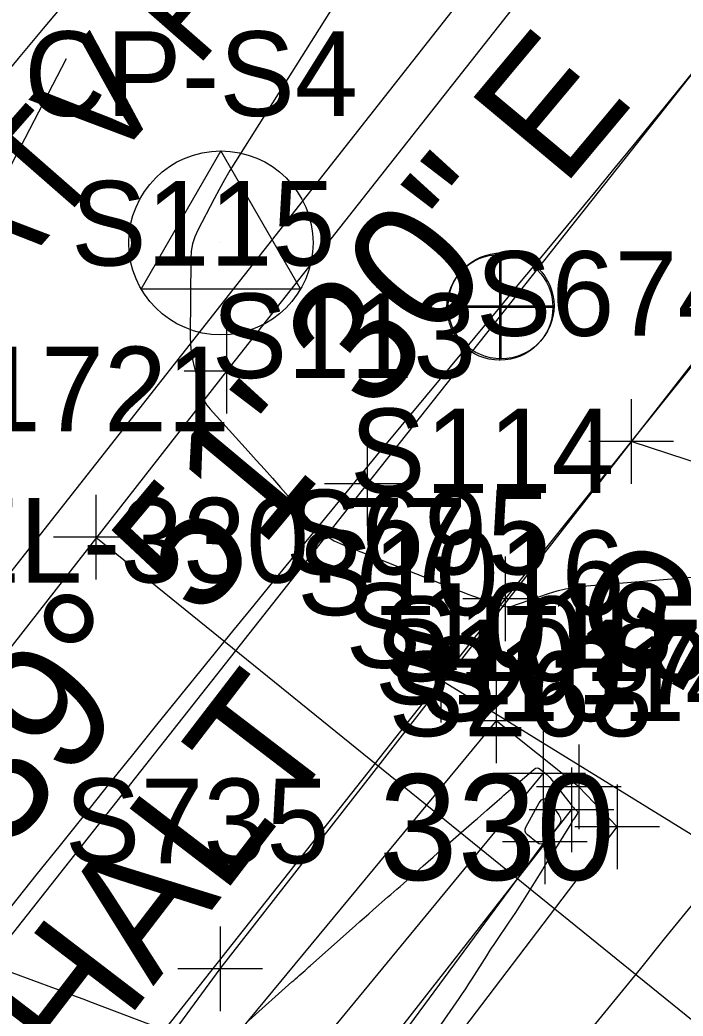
# Model space of a CAD drawing. Extents: x 816928 to 825690, y 436959 to 448212.
# Drawn here: x 819251.82 to 819283.14, y 445565.31 to 445612.41 of the extents above; entities that cross this region are included whole.
import ezdxf

# ---------------------------------------------------------------- set-up
doc = ezdxf.new("R2010")
doc.units = 0
for name, color, linetype in [('SURVEY - CENTERLINE - Preliminary', 7, 'Continuous'), ('SURVEY - CENTERLINE - Preliminary - Development', 7, 'Continuous'), ('SURVEY - CENTERLINE - Preliminary Text', 7, 'Continuous'), ('SURVEY - CONTOURS - Index with Text', 7, 'Continuous'), ('SURVEY - CONTOURS - Intermediate with optional Text', 7, 'Continuous'), ('SURVEY - CONTROL with Text', 7, 'Continuous'), ('SURVEY - DRAINAGE - Area Shapes', 7, 'Continuous'), ('SURVEY - DTM - Breaklines', 7, 'Continuous'), ('SURVEY - DTM - Breaklines - Points - Locators', 7, 'Continuous'), ('SURVEY - DTM - Breaklines - Points - Numbers', 7, 'Continuous'), ('SURVEY - PROPERTY - Parcels', 7, 'Continuous'), ('SURVEY - PROPERTY - ROW Lines', 7, 'Continuous'), ('SURVEY - TRANSPORTATION - Features', 7, 'Continuous'), ('SURVEY - TRANSPORTATION - Features - Points - Locators', 7, 'Continuous'), ('SURVEY - TRANSPORTATION - Features - Points - Numbers', 7, 'Continuous'), ('SURVEY - TRANSPORTATION - Features Text', 7, 'Continuous'), ('SURVEY - TRANSPORTATION - Roads', 7, 'Continuous'), ('SURVEY - TRANSPORTATION - Roads - Points - Locators', 7, 'Continuous'), ('SURVEY - TRANSPORTATION - Roads - Points - Numbers', 7, 'Continuous'), ('SURVEY - TRANSPORTATION - Roads Text', 7, 'Continuous'), ('SURVEY - UTILITIES - Cable (Underground) with Text', 7, 'Continuous'), ('SURVEY - UTILITIES - Gas - Points - Locators', 7, 'Continuous'), ('SURVEY - UTILITIES - Gas - Points - Numbers', 7, 'Continuous'), ('SURVEY - UTILITIES - Gas with Text', 7, 'Continuous'), ('SURVEY - UTILITIES - Poles and Miscellaneous - Points - Elevations', 7, 'Continuous'), ('SURVEY - UTILITIES - Water - Points - Locators', 7, 'Continuous'), ('SURVEY - UTILITIES - Water - Points - Numbers', 7, 'Continuous'), ('SURVEY - UTILITIES - Water with Text', 7, 'Continuous'), ('SURVEY - VEGETATION - Features - Points - Locators', 7, 'Continuous'), ('SURVEY - VEGETATION - Features - Points - Numbers', 7, 'Continuous'), ('SURVEY - VEGETATION - Features with Text', 7, 'Continuous')]:
    doc.layers.add(name, color=color, linetype=linetype)

msp = doc.modelspace()

# ---------------------------------------------------------------- linework, layer by layer
at = {"layer": 'SURVEY - CENTERLINE - Preliminary'}
msp.add_line((819274.472, 445598.813), (819274.528, 445598.88), dxfattribs=at)
for centre, radius, start, end in [((818575.983, 446182.091), 910, 320.141729, 331.568854), ((818575.983, 446182.091), 910, 320.141729, 331.568854), ((820425.92, 444637.477), 1500, 140.141729, 144.598464), ((820425.92, 444637.477), 1500, 140.141729, 144.598464)]:
    msp.add_arc(centre, radius, start, end, dxfattribs=at)
at = {"layer": 'SURVEY - CENTERLINE - Preliminary - Development'}
for p, q in [((819274.472, 445601.313), (819274.472, 445596.313)), ((819274.528, 445601.38), (819274.528, 445596.38)), ((819276.972, 445598.813), (819271.972, 445598.813)), ((819277.028, 445598.88), (819272.028, 445598.88))]:
    msp.add_line(p, q, dxfattribs=at)
at = {"layer": 'SURVEY - CENTERLINE - Preliminary Text'}
for p, q in [((819274.472, 445598.813), (819274.472, 445598.813)), ((819274.528, 445598.88), (819274.528, 445598.88))]:
    msp.add_line(p, q, dxfattribs=at)
for centre in [(819274.491, 445598.819), (819274.547, 445598.887)]:
    msp.add_circle(centre, 2.5, dxfattribs=at)
at = {"layer": 'SURVEY - CONTOURS - Index with Text'}
for points in [[(819254, 445610.57), (819250.305, 445603.462)], [(819262.638, 445565.11), (819264.668, 445566.926), (819264.754, 445567.002), (819264.839, 445567.078), (819264.925, 445567.153), (819265.01, 445567.229), (819265.291, 445567.475), (819265.351, 445567.528), (819265.411, 445567.581), (819265.471, 445567.634), (819265.531, 445567.687), (819267.67, 445569.593), (819267.878, 445569.778), (819268.087, 445569.962), (819268.296, 445570.146), (819268.505, 445570.33), (819269.19, 445570.928), (819269.337, 445571.057), (819269.483, 445571.185), (819269.629, 445571.314), (819269.775, 445571.443), (819270.864, 445572.41), (819271.098, 445572.617), (819271.332, 445572.823), (819271.567, 445573.029), (819271.802, 445573.234), (819273.281, 445574.522), (819273.431, 445574.653), (819273.581, 445574.784), (819273.73, 445574.915), (819273.88, 445575.047), (819274.367, 445575.477), (819274.471, 445575.569), (819274.576, 445575.661), (819274.681, 445575.753), (819274.786, 445575.844), (819276.093, 445576.977), (819276.168, 445577.026), (819276.244, 445577.044), (819276.321, 445577.029), (819276.398, 445576.983), (819276.651, 445576.782), (819276.704, 445576.737), (819276.754, 445576.69), (819276.801, 445576.639), (819276.845, 445576.586), (819277.85, 445575.303), (819277.886, 445575.258), (819277.923, 445575.215), (819277.962, 445575.172), (819278.002, 445575.131), (819278.135, 445574.997), (819278.157, 445574.968), (819278.166, 445574.937), (819278.163, 445574.905), (819278.146, 445574.873), (819277.977, 445574.622), (819277.941, 445574.568), (819277.906, 445574.514), (819277.871, 445574.46), (819277.836, 445574.405), (819277.115, 445573.241), (819276.96, 445572.992), (819276.806, 445572.742), (819276.651, 445572.493), (819276.497, 445572.244), (819275.556, 445570.726), (819275.393, 445570.467), (819275.228, 445570.21), (819275.059, 445569.955), (819274.888, 445569.703), (819274.323, 445568.88), (819274.203, 445568.703), (819274.085, 445568.525), (819273.968, 445568.346), (819273.853, 445568.165), (819273.162, 445567.073), (819273.012, 445566.839), (819272.861, 445566.607), (819272.707, 445566.377), (819272.55, 445566.148), (819271.594, 445564.765)], [(819275.719, 445574.246), (819276.342, 445575.387), (819276.455, 445575.538), (819276.573, 445575.595), (819276.699, 445575.555), (819276.831, 445575.42), (819277.274, 445574.824), (819277.344, 445574.696), (819277.367, 445574.569), (819277.34, 445574.443), (819277.266, 445574.318), (819276.685, 445573.584), (819276.577, 445573.481), (819276.463, 445573.438), (819276.342, 445573.456), (819276.214, 445573.534), (819275.788, 445573.886), (819275.715, 445573.966), (819275.679, 445574.052), (819275.681, 445574.145), (819275.719, 445574.246)], [(819251.448, 445567.368), (819253.488, 445566.614), (819253.925, 445566.452), (819254.361, 445566.289), (819254.797, 445566.126), (819255.233, 445565.961), (819258.48, 445564.729)]]:
    msp.add_lwpolyline(points, dxfattribs=at)
at = {"layer": 'SURVEY - CONTOURS - Intermediate with optional Text'}
msp.add_lwpolyline([(819270.629, 445619.417), (819262.003, 445605.715), (819261.736, 445605.281), (819261.478, 445604.841), (819261.229, 445604.397), (819260.99, 445603.947), (819260.222, 445602.47), (819260.077, 445602.148), (819259.974, 445601.816), (819259.911, 445601.475), (819259.889, 445601.123), (819259.869, 445597.428), (819259.879, 445597.069), (819259.912, 445596.713), (819259.968, 445596.359), (819260.047, 445596.009), (819260.342, 445594.868), (819260.419, 445594.631), (819260.522, 445594.408), (819260.652, 445594.2), (819260.808, 445594.005), (819262.601, 445592.02), (819262.985, 445591.594), (819263.367, 445591.166), (819263.748, 445590.738), (819264.127, 445590.308), (819265.586, 445588.647), (819265.915, 445588.314), (819266.276, 445588.026), (819266.668, 445587.784), (819267.092, 445587.586), (819272.169, 445585.571), (819272.436, 445585.466), (819272.703, 445585.365), (819272.971, 445585.266), (819273.241, 445585.169), (819274.457, 445584.74), (819274.478, 445584.733), (819274.5, 445584.727), (819274.521, 445584.721), (819274.543, 445584.716), (819274.615, 445584.7), (819274.63, 445584.697), (819274.645, 445584.693), (819274.661, 445584.69), (819274.676, 445584.687), (819274.83, 445584.653), (819274.862, 445584.648), (819274.895, 445584.648), (819274.927, 445584.652), (819274.959, 445584.661), (819276.793, 445585.29), (819277.188, 445585.412), (819277.589, 445585.51), (819277.995, 445585.582), (819278.407, 445585.63), (819283.55, 445586.065)], dxfattribs=at)
at = {"layer": 'SURVEY - CONTROL with Text'}
for p, q in [((819261.315, 445606.216), (819257.547, 445599.691)), ((819265.082, 445599.691), (819261.315, 445606.216)), ((819261.315, 445601.866), (819261.315, 445601.866)), ((819257.547, 445599.691), (819265.082, 445599.691))]:
    msp.add_line(p, q, dxfattribs=at)
msp.add_circle((819261.315, 445601.866), 4.35, dxfattribs=at)
at = {"layer": 'SURVEY - DRAINAGE - Area Shapes'}
msp.add_line((819274.472, 445598.813), (819274.528, 445598.88), dxfattribs=at)
for centre, radius, start, end in [((818575.983, 446182.091), 910, 320.141729, 331.568854), ((820425.92, 444637.477), 1500, 140.141729, 144.598464)]:
    msp.add_arc(centre, radius, start, end, dxfattribs=at)
at = {"layer": 'SURVEY - DTM - Breaklines'}
for points in [[(819380.404, 445755.141), (819355.578, 445711.888), (819328.616, 445669.931), (819299.268, 445629.736), (819268.215, 445590.476), (819237.204, 445551.148), (819207.272, 445511.316), (819178.097, 445471.355), (819148.961, 445430.516), (819120.831, 445389.41), (819092.595, 445348.525), (819063.764, 445307.701), (819034.576, 445266.965), (819005.716, 445226.512), (818977.706, 445187.397)], [(819115.743, 445352.623), (819116.501, 445348.532), (819118.762, 445346.334), (819121.805, 445346.034), (819151.273, 445387.488), (819170.031, 445419.1), (819198.511, 445465.669), (819205.76, 445465.616), (819229.822, 445502.933), (819247.854, 445531.915), (819280.031, 445574.26), (819278.221, 445576.151), (819274.311, 445579.267), (819242.916, 445541.289), (819216.533, 445504.811), (819186.916, 445462.104), (819160.05, 445422.329), (819116.797, 445352.316)], [(819118.629, 445350.898), (819165.289, 445424.101), (819196.182, 445467.268), (819224.41, 445508.114), (819242.999, 445536.052), (819276.537, 445576.778)], [(819121.197, 445348.347), (819148.072, 445388.457), (819146.917, 445389.221), (819167.079, 445422.999), (819197.484, 445466.128), (819224.892, 445507.372), (819245.683, 445533.866), (819277.871, 445575.058)]]:
    msp.add_lwpolyline(points, dxfattribs=at)
at = {"layer": 'SURVEY - DTM - Breaklines - Points - Locators'}
for p, q in [((819268.215, 445592.476), (819268.215, 445588.476)), ((819270.215, 445590.476), (819266.215, 445590.476)), ((819274.311, 445581.267), (819274.311, 445577.267)), ((819276.311, 445579.267), (819272.311, 445579.267)), ((819276.537, 445578.778), (819276.537, 445574.778)), ((819278.221, 445578.151), (819278.221, 445574.151)), ((819277.871, 445577.058), (819277.871, 445573.058)), ((819278.537, 445576.778), (819274.537, 445576.778)), ((819280.221, 445576.151), (819276.221, 445576.151)), ((819280.031, 445576.26), (819280.031, 445572.26)), ((819279.871, 445575.058), (819275.871, 445575.058)), ((819282.031, 445574.26), (819278.031, 445574.26))]:
    msp.add_line(p, q, dxfattribs=at)
at = {"layer": 'SURVEY - PROPERTY - Parcels'}
for radius, end in [(1525, 144.574738), (1475, 144.598464)]:
    msp.add_arc((820425.92, 444637.477), radius, 140.141729, end, dxfattribs=at)
at = {"layer": 'SURVEY - PROPERTY - ROW Lines'}
for radius, end in [(1525, 144.574738), (1525, 144.574738), (1475, 144.598464), (1475, 144.598464)]:
    msp.add_arc((820425.92, 444637.477), radius, 140.141729, end, dxfattribs=at)
at = {"layer": 'SURVEY - TRANSPORTATION - Features'}
for points in [[(819290.371, 445604.569), (819297.011, 445596.352), (819322.259, 445582.842), (819319.545, 445574.083), (819291.995, 445588.779), (819280.694, 445592.472)], [(819318.745, 445574.129), (819306.664, 445553.05), (819293.667, 445563.515), (819294.599, 445567.059), (819271.707, 445581.193)]]:
    msp.add_lwpolyline(points, dxfattribs=at)
at = {"layer": 'SURVEY - TRANSPORTATION - Features - Points - Locators'}
for p, q in [((819280.694, 445594.472), (819280.694, 445590.472)), ((819282.694, 445592.472), (819278.694, 445592.472)), ((819271.707, 445583.193), (819271.707, 445579.193)), ((819273.707, 445581.193), (819269.707, 445581.193))]:
    msp.add_line(p, q, dxfattribs=at)
at = {"layer": 'SURVEY - TRANSPORTATION - Roads'}
for points in [[(819372.417, 445760.729), (819347.536, 445716.465), (819327.358, 445684.931), (819320.732, 445674.576), (819313.086, 445663.907), (819291.72, 445634.092), (819261.573, 445595.794), (819230.52, 445556.026), (819202.59, 445519.473), (819200.025, 445516.115), (819183.78, 445493.817), (819171.491, 445476.948), (819142.501, 445435.003), (819121.554, 445405.003), (819114.313, 445394.631), (819108.813, 445386.861), (819085.629, 445354.103), (819056.538, 445311.65), (819028.029, 445272.038), (818998.985, 445231.035), (818970.783, 445191.785), (818984.089, 445181.723)], [(819389.734, 445754.855), (819362.957, 445707.555), (819358.085, 445699.888), (819346.624, 445681.852), (819335.583, 445664.476), (819305.378, 445623.327), (819290.371, 445604.569), (819280.694, 445592.472), (819274.745, 445585.035), (819271.707, 445581.193), (819243.267, 445545.212), (819213.411, 445505.8), (819184.164, 445465.705), (819155.799, 445425.75), (819127.747, 445384.791), (819108.123, 445356.526), (819098.861, 445343.186), (819090.273, 445331.1), (819070.114, 445302.733), (819042.351, 445263.277), (819039.074, 445258.681), (819026.695, 445241.322), (819012.76, 445221.779), (818984.089, 445181.723)]]:
    msp.add_lwpolyline(points, dxfattribs=at)
at = {"layer": 'SURVEY - TRANSPORTATION - Roads - Points - Locators'}
for p, q in [((819261.573, 445597.794), (819261.573, 445593.794)), ((819263.573, 445595.794), (819259.573, 445595.794)), ((819274.745, 445587.035), (819274.745, 445583.035)), ((819276.745, 445585.035), (819272.745, 445585.035))]:
    msp.add_line(p, q, dxfattribs=at)
at = {"layer": 'SURVEY - UTILITIES - Gas - Points - Locators'}
for p, q in [((819255.402, 445589.957), (819255.402, 445585.957)), ((819257.402, 445587.957), (819253.402, 445587.957))]:
    msp.add_line(p, q, dxfattribs=at)
at = {"layer": 'SURVEY - UTILITIES - Gas with Text'}
for points in [[(818968.105, 445195.328), (818969.738, 445197.267), (819012.001, 445253.658), (819064.107, 445326.037), (819122.078, 445408.8), (819183.152, 445497.068), (819237.635, 445568.809), (819293.129, 445639.42), (819349.073, 445723.122), (819383.091, 445785.202)], [(819255.402, 445587.957), (819296.534, 445554.619), (819316.051, 445542.116), (819330.474, 445549.407), (819356.758, 445566.69)]]:
    msp.add_lwpolyline(points, dxfattribs=at)
at = {"layer": 'SURVEY - UTILITIES - Water - Points - Locators'}
for p, q in [((819261.281, 445569.542), (819261.281, 445565.542)), ((819263.281, 445567.542), (819259.281, 445567.542))]:
    msp.add_line(p, q, dxfattribs=at)
at = {"layer": 'SURVEY - UTILITIES - Water with Text'}
msp.add_lwpolyline([(818803.235, 444799.745), (818822.09, 444847.157), (818840.807, 444894.989), (818859.419, 444943.113), (818878.417, 444989.731), (818897.247, 445035.659), (818918.394, 445078.737), (818943.016, 445121.017), (818943.424, 445156.253), (818947.564, 445166.115), (818971.795, 445201.192), (819041.117, 445261.897), (819085.564, 445324.056), (819114.437, 445364.745), (819142.589, 445406.123), (819261.281, 445567.542), (819325.961, 445650.567), (819357.336, 445697.813), (819381.766, 445739.87), (819404.905, 445782.998)], dxfattribs=at)
at = {"layer": 'SURVEY - VEGETATION - Features - Points - Locators'}
for p, q in [((819276.613, 445575.546), (819276.613, 445571.546)), ((819278.613, 445573.546), (819274.613, 445573.546))]:
    msp.add_line(p, q, dxfattribs=at)
at = {"layer": 'SURVEY - VEGETATION - Features with Text'}
msp.add_line((819228.505, 445508.335), (819276.613, 445573.546), dxfattribs=at)

# ---------------------------------------------------------------- texts
at = {"layer": 'SURVEY - CENTERLINE - Preliminary Text'}
msp.add_text('N 39%%d 51\' 30" E', height=6, rotation=50.1417, dxfattribs=at).set_placement((819245.984, 445566.742))
at = {"layer": 'SURVEY - CONTOURS - Index with Text'}
msp.add_text('330', height=5, dxfattribs=at).set_placement((819268.773, 445571.746))
at = {"layer": 'SURVEY - CONTROL with Text'}
msp.add_text('CP-S4', height=4, dxfattribs=at).set_placement((819252.027, 445607.866))
at = {"layer": 'SURVEY - DTM - Breaklines - Points - Numbers'}
for s, p in [('S113', (819260.879, 445595.476)), ('S1016', (819264.913, 445584.267)), ('S1018', (819267.202, 445581.778)), ('S1015', (819268.933, 445581.151)), ('S1017', (819268.583, 445580.058)), ('S1014', (819270.743, 445579.26))]:
    msp.add_text(s, height=4, dxfattribs=at).set_placement(p)
at = {"layer": 'SURVEY - TRANSPORTATION - Features - Points - Numbers'}
for s, p in [('S674', (819273.358, 445597.472)), ('S695', (819264.371, 445586.193))]:
    msp.add_text(s, height=4, dxfattribs=at).set_placement(p)
at = {"layer": 'SURVEY - TRANSPORTATION - Features Text'}
msp.add_text('GRV. DR.', height=5, rotation=330.7672, dxfattribs=at).set_placement((819277.597, 445583.831))
at = {"layer": 'SURVEY - TRANSPORTATION - Roads - Points - Numbers'}
for s, p in [('S115', (819254.237, 445600.794)), ('S114', (819267.409, 445590.035))]:
    msp.add_text(s, height=4, dxfattribs=at).set_placement(p)
at = {"layer": 'SURVEY - TRANSPORTATION - Roads Text'}
msp.add_text('ASPHALT', height=6, rotation=52.5394, dxfattribs=at).set_placement((819244.826, 445549.364))
at = {"layer": 'SURVEY - UTILITIES - Cable (Underground) with Text'}
msp.add_text('CATV PED.', height=5.0001, rotation=48.7665, dxfattribs=at).set_placement((819247.146, 445595.26))
at = {"layer": 'SURVEY - UTILITIES - Gas - Points - Numbers'}
msp.add_text('S1721', height=4, dxfattribs=at).set_placement((819246.272, 445592.957))
at = {"layer": 'SURVEY - UTILITIES - Poles and Miscellaneous - Points - Elevations'}
msp.add_text('EL-330.77', height=4, dxfattribs=at).set_placement((819248.236, 445585.809))
at = {"layer": 'SURVEY - UTILITIES - Water - Points - Numbers'}
msp.add_text('S735', height=4, dxfattribs=at).set_placement((819253.945, 445572.542))
at = {"layer": 'SURVEY - VEGETATION - Features - Points - Numbers'}
msp.add_text('S268', height=4, dxfattribs=at).set_placement((819269.229, 445578.546))

doc.saveas('drawing.dxf')
